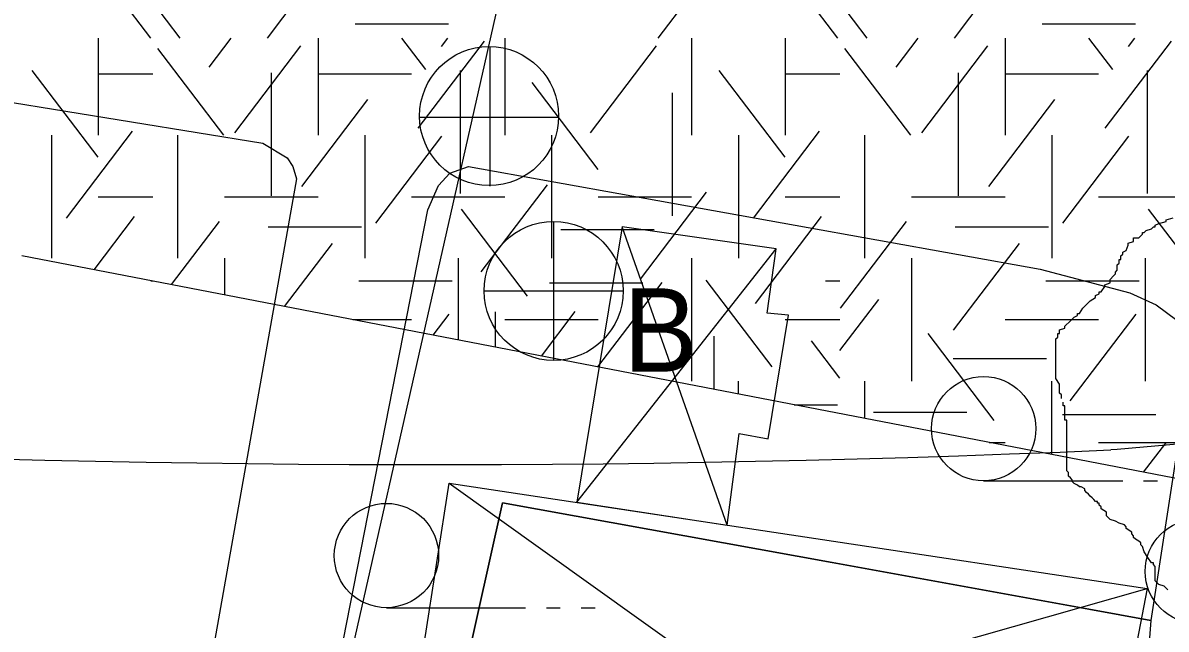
# Model space of a CAD drawing. Extents: x 419101 to 420177, y 4451541 to 4452254.
# Drawn here: x 419766.26 to 419782.7, y 4451874.81 to 4451883.53 of the extents above; entities that cross this region are included whole.
import ezdxf

# ---------------------------------------------------------------- set-up
doc = ezdxf.new("R2010")
doc.units = 0
for name, color, linetype in [('1_PLAN_ONAMA_SINIRI', 7, 'Continuous'), ('2_KADASTRO', 7, 'Continuous'), ('3_HALİHAZIR', 7, 'Continuous'), ('Level 10', 7, 'Continuous'), ('Level 3', 7, 'Continuous'), ('Level 41', 7, 'Continuous'), ('Level 62', 7, 'Continuous')]:
    doc.layers.add(name, color=color, linetype=linetype)

msp = doc.modelspace()

# ---------------------------------------------------------------- linework, layer by layer
at = {"layer": '1_PLAN_ONAMA_SINIRI'}
msp.add_line((419781.992, 4451877.39), (419781.902, 4451877.384), dxfattribs=at)
msp.add_lwpolyline([(419842.849, 4451882.779), (419781.992, 4451877.39)], dxfattribs=at)
msp.add_arc((419772.081, 4452104.769), 227.597, 260.70974, 272.47309, dxfattribs=at)
at = {"layer": '2_KADASTRO'}
for points in [[(419759.111, 4451874.282), (419762.553, 4451893.022), (419762.975, 4451895.317), (419776.403, 4451891.967), (419783.47, 4451890.204), (419784.306, 4451886.857), (419782.476, 4451874.932), (419781.586, 4451875.093), (419777.895, 4451875.763), (419773.151, 4451876.624), (419772.058, 4451871.72), (419771.471, 4451871.836), (419759.378, 4451874.229)], [(419772.058, 4451871.72), (419773.151, 4451876.624), (419777.895, 4451875.763), (419781.586, 4451875.093), (419782.476, 4451874.932), (419782.31, 4451872.739), (419781.942, 4451869.764), (419781.675, 4451869.818), (419781.384, 4451869.876), (419780.697, 4451870.01)]]:
    msp.add_lwpolyline(points, close=True, dxfattribs=at)
at = {"layer": '3_HALİHAZIR'}
for p, q in [((419772.975, 4451881.178), (419772.975, 4451883.178)), ((419771.955, 4451882.168), (419773.955, 4451882.168)), ((419773.888, 4451880.671), (419773.888, 4451878.671)), ((419776.382, 4451876.304), (419774.874, 4451880.593)), ((419774.221, 4451876.631), (419777.087, 4451880.275)), ((419772.888, 4451879.671), (419774.888, 4451879.671)), ((419772.387, 4451876.908), (419781.465, 4451870.409)), ((419780.071, 4451876.94), (419782.071, 4451876.94)), ((419782.371, 4451876.94), (419782.571, 4451876.94)), ((419771.676, 4451872.341), (419782.424, 4451875.392)), ((419771.484, 4451875.115), (419773.484, 4451875.115)), ((419773.784, 4451875.115), (419773.984, 4451875.115)), ((419774.284, 4451875.115), (419774.484, 4451875.115))]:
    msp.add_line(p, q, dxfattribs=at)
for points in [[(419759.591, 4451874.725), (419758.475, 4451874.972), (419759.632, 4451880.219), (419759.97, 4451880.958), (419761.907, 4451882.947), (419762.075, 4451883.015), (419762.146, 4451883.021), (419769.704, 4451881.794), (419770.058, 4451881.585), (419770.137, 4451881.459), (419770.191, 4451881.282), (419768.71, 4451872.926)], [(419770.457, 4451872.581), (419772.077, 4451880.838), (419772.233, 4451881.185), (419772.396, 4451881.366), (419772.664, 4451881.458), (419780.886, 4451879.982), (419782.172, 4451879.643), (419782.552, 4451879.47), (419782.85, 4451879.248)]]:
    msp.add_lwpolyline(points, dxfattribs=at)
for points in [[(419774.221, 4451876.631), (419776.382, 4451876.304), (419776.556, 4451877.621), (419776.975, 4451877.542), (419777.267, 4451879.323), (419776.958, 4451879.351), (419777.087, 4451880.275), (419774.874, 4451880.593)], [(419771.676, 4451872.341), (419772.387, 4451876.908), (419782.424, 4451875.392), (419781.465, 4451870.409)]]:
    msp.add_lwpolyline(points, close=True, dxfattribs=at)
for centre, radius in [((419772.96, 4451882.186), 1), ((419773.888, 4451879.671), 1), ((419780.071, 4451877.69), 0.75), ((419771.484, 4451875.865), 0.75), ((419783.143, 4451875.637), 0.75)]:
    msp.add_circle(centre, radius, dxfattribs=at)
at = {"layer": 'Level 10'}
msp.add_lwpolyline([(419822.258, 4451726.513), (419833.485, 4451749.755), (419825.109, 4451754.045), (419837.782, 4451781.64), (419829.05, 4451785.752), (419831.545, 4451792.367), (419821.03, 4451797.373), (419817.644, 4451790.221), (419809.089, 4451795.049), (419767.565, 4451777.886), (419755.344, 4451810.228), (419782.076, 4451819.704), (419780.107, 4451841.764), (419779.395, 4451861.43), (419768.523, 4451863.576), (419780.134, 4451914.941)], dxfattribs=at)
at = {"layer": 'Level 3'}
for points in [[(419781.189, 4451878.124), (419781.189, 4451878.15), (419781.189, 4451878.175), (419781.163, 4451878.201), (419781.163, 4451878.227), (419781.163, 4451878.253), (419781.163, 4451878.279), (419781.163, 4451878.305), (419781.163, 4451878.331), (419781.111, 4451878.409), (419781.111, 4451878.487), (419781.111, 4451878.513), (419781.111, 4451878.591), (419781.111, 4451878.669), (419781.111, 4451878.695), (419781.111, 4451878.721), (419781.111, 4451878.747), (419781.111, 4451878.773), (419781.111, 4451878.799), (419781.111, 4451878.825), (419781.111, 4451878.851), (419781.111, 4451878.877), (419781.111, 4451878.903), (419781.111, 4451878.981), (419781.137, 4451879.006), (419781.137, 4451879.032), (419781.137, 4451879.058), (419781.163, 4451879.058), (419781.163, 4451879.084), (419781.163, 4451879.11), (419781.241, 4451879.136), (419781.241, 4451879.162), (419781.319, 4451879.24), (419781.371, 4451879.292), (419781.422, 4451879.318), (419781.422, 4451879.344), (419781.448, 4451879.344), (419781.5, 4451879.422), (419781.552, 4451879.474), (419781.604, 4451879.526), (419781.682, 4451879.578), (419781.682, 4451879.604), (419781.734, 4451879.63), (419781.734, 4451879.656), (419781.76, 4451879.656), (419781.812, 4451879.734), (419781.812, 4451879.76), (419781.889, 4451879.786), (419781.889, 4451879.811), (419781.889, 4451879.837), (419781.941, 4451879.889), (419781.967, 4451879.915), (419781.967, 4451879.941), (419781.993, 4451879.967), (419781.993, 4451879.993), (419781.993, 4451880.019), (419781.993, 4451880.045), (419782.019, 4451880.071), (419782.019, 4451880.097), (419782.019, 4451880.123), (419782.045, 4451880.123), (419782.045, 4451880.149), (419782.045, 4451880.175), (419782.071, 4451880.201), (419782.071, 4451880.227), (419782.123, 4451880.253), (419782.149, 4451880.331), (419782.149, 4451880.357), (419782.227, 4451880.383), (419782.227, 4451880.409), (419782.227, 4451880.435), (419782.304, 4451880.435), (419782.356, 4451880.487), (419782.356, 4451880.513), (419782.382, 4451880.513), (419782.408, 4451880.539), (419782.486, 4451880.565), (419782.512, 4451880.591), (419782.538, 4451880.591), (419782.538, 4451880.617), (419782.59, 4451880.642), (419782.694, 4451880.668), (419782.694, 4451880.694), (419782.797, 4451880.72)], [(419782.72, 4451875.371), (419782.668, 4451875.423), (419782.59, 4451875.449), (419782.564, 4451875.475), (419782.538, 4451875.501), (419782.538, 4451875.527), (419782.538, 4451875.605), (419782.538, 4451875.683), (419782.538, 4451875.708), (419782.512, 4451875.734), (419782.512, 4451875.76), (419782.486, 4451875.76), (419782.434, 4451875.838), (419782.382, 4451875.916), (419782.356, 4451875.994), (419782.33, 4451876.02), (419782.33, 4451876.046), (419782.304, 4451876.072), (419782.253, 4451876.098), (419782.227, 4451876.124), (419782.227, 4451876.15), (419782.201, 4451876.176), (419782.201, 4451876.202), (419782.123, 4451876.254), (419782.123, 4451876.28), (419782.097, 4451876.306), (419782.019, 4451876.332), (419781.967, 4451876.358), (419781.889, 4451876.384), (419781.863, 4451876.41), (419781.838, 4451876.436), (419781.838, 4451876.462), (419781.838, 4451876.488), (419781.76, 4451876.539), (419781.76, 4451876.565), (419781.734, 4451876.591), (419781.734, 4451876.617), (419781.708, 4451876.617), (419781.708, 4451876.643), (419781.682, 4451876.643), (419781.656, 4451876.669), (419781.63, 4451876.695), (419781.604, 4451876.721), (419781.578, 4451876.747), (419781.552, 4451876.773), (419781.526, 4451876.799), (419781.526, 4451876.825), (419781.474, 4451876.851), (419781.448, 4451876.851), (419781.422, 4451876.877), (419781.371, 4451876.903), (419781.345, 4451876.929), (419781.345, 4451876.955), (419781.319, 4451876.981), (419781.293, 4451877.007), (419781.293, 4451877.033), (419781.293, 4451877.059), (419781.267, 4451877.085), (419781.267, 4451877.111), (419781.267, 4451877.137), (419781.267, 4451877.215), (419781.267, 4451877.267), (419781.267, 4451877.293), (419781.267, 4451877.319), (419781.267, 4451877.344), (419781.267, 4451877.37), (419781.267, 4451877.396), (419781.267, 4451877.422), (419781.267, 4451877.448), (419781.267, 4451877.474), (419781.267, 4451877.5), (419781.267, 4451877.526), (419781.267, 4451877.552), (419781.267, 4451877.578), (419781.267, 4451877.604), (419781.267, 4451877.63), (419781.267, 4451877.656), (419781.267, 4451877.682), (419781.267, 4451877.76), (419781.267, 4451877.786), (419781.267, 4451877.812), (419781.241, 4451877.812), (419781.241, 4451877.838), (419781.241, 4451877.864), (419781.241, 4451877.89), (419781.241, 4451877.916), (419781.241, 4451877.942), (419781.241, 4451877.968), (419781.241, 4451877.994), (419781.241, 4451878.02), (419781.215, 4451878.02), (419781.215, 4451878.046), (419781.215, 4451878.072)]]:
    msp.add_lwpolyline(points, dxfattribs=at)
at = {"layer": 'Level 41'}
for p, q in [((419768.095, 4451883.307), (419767.293, 4451884.363)), ((419769.771, 4451883.307), (419770.6, 4451884.398)), ((419777.974, 4451883.307), (419777.172, 4451884.363)), ((419779.65, 4451883.307), (419780.479, 4451884.398)), ((419775.391, 4451883.307), (419775.928, 4451884.013)), ((419768.518, 4451883.307), (419768.124, 4451883.825)), ((419778.397, 4451883.307), (419778.003, 4451883.825)), ((419771.033, 4451883.513), (419772.376, 4451883.513)), ((419780.912, 4451883.513), (419782.255, 4451883.513)), ((419767.336, 4451883.307), (419767.336, 4451881.909)), ((419767.336, 4451883.307), (419767.336, 4451881.909)), ((419768.934, 4451882.89), (419769.251, 4451883.307)), ((419770.5, 4451883.307), (419770.5, 4451881.909)), ((419772.049, 4451882.855), (419771.705, 4451883.307)), ((419772.275, 4451883.187), (419772.366, 4451883.307)), ((419773.186, 4451883.307), (419773.186, 4451881.909)), ((419775.872, 4451883.307), (419775.872, 4451881.909)), ((419777.215, 4451883.307), (419777.215, 4451881.909)), ((419777.215, 4451883.307), (419777.215, 4451881.909)), ((419778.813, 4451882.89), (419779.13, 4451883.307)), ((419780.379, 4451883.307), (419780.379, 4451881.909)), ((419781.928, 4451882.855), (419781.584, 4451883.307)), ((419782.154, 4451883.187), (419782.245, 4451883.307)), ((419769.145, 4451881.909), (419768.196, 4451883.159)), ((419769.305, 4451881.944), (419770.254, 4451883.194)), ((419771.942, 4451882.013), (419772.892, 4451883.263)), ((419774.419, 4451881.944), (419775.368, 4451883.194)), ((419779.024, 4451881.909), (419778.075, 4451883.159)), ((419779.184, 4451881.944), (419780.133, 4451883.194)), ((419781.821, 4451882.013), (419782.771, 4451883.263)), ((419767.337, 4451881.593), (419766.388, 4451882.842)), ((419767.336, 4451882.793), (419768.124, 4451882.793)), ((419769.825, 4451882.805), (419769.825, 4451881.038)), ((419770.5, 4451882.793), (419771.843, 4451882.793)), ((419772.542, 4451882.84), (419772.542, 4451881.073)), ((419777.216, 4451881.593), (419776.267, 4451882.842)), ((419777.215, 4451882.793), (419778.003, 4451882.793)), ((419779.704, 4451882.805), (419779.704, 4451881.038)), ((419780.379, 4451882.793), (419781.722, 4451882.793)), ((419782.421, 4451882.84), (419782.421, 4451881.073)), ((419774.526, 4451881.418), (419773.577, 4451882.667)), ((419775.59, 4451882.519), (419775.59, 4451880.752)), ((419770.265, 4451881.172), (419771.214, 4451882.422)), ((419780.144, 4451881.172), (419781.093, 4451882.422)), ((419766.885, 4451880.716), (419767.834, 4451881.966)), ((419776.764, 4451880.716), (419777.713, 4451881.966)), ((419766.665, 4451881.909), (419766.665, 4451880.142)), ((419766.665, 4451881.909), (419766.665, 4451880.142)), ((419768.486, 4451880.142), (419768.486, 4451881.909)), ((419771.172, 4451881.909), (419771.172, 4451880.142)), ((419771.331, 4451880.647), (419772.28, 4451881.897)), ((419773.858, 4451881.909), (419773.858, 4451880.142)), ((419776.544, 4451881.909), (419776.544, 4451880.142)), ((419776.544, 4451881.909), (419776.544, 4451880.142)), ((419778.365, 4451880.142), (419778.365, 4451881.909)), ((419781.051, 4451881.909), (419781.051, 4451880.142)), ((419781.21, 4451880.647), (419782.159, 4451881.897)), ((419772.848, 4451879.946), (419773.799, 4451881.195)), ((419767.336, 4451881.025), (419768.124, 4451881.025)), ((419769.157, 4451881.025), (419770.5, 4451881.025)), ((419771.843, 4451881.025), (419773.186, 4451881.025)), ((419774.529, 4451881.025), (419775.872, 4451881.025)), ((419775.139, 4451879.841), (419776.088, 4451881.091)), ((419777.215, 4451881.025), (419778.003, 4451881.025)), ((419779.036, 4451881.025), (419780.379, 4451881.025)), ((419781.722, 4451881.025), (419783.065, 4451881.025)), ((419773.514, 4451879.596), (419772.564, 4451880.845)), ((419783.393, 4451879.596), (419782.443, 4451880.845)), ((419767.28, 4451879.976), (419767.861, 4451880.739)), ((419768.392, 4451879.761), (419769.083, 4451880.67)), ((419776.79, 4451879.49), (419777.74, 4451880.739)), ((419778.013, 4451879.421), (419778.962, 4451880.67)), ((419769.781, 4451880.591), (419771.124, 4451880.591)), ((419773.989, 4451880.555), (419775.332, 4451880.555)), ((419779.66, 4451880.591), (419781.003, 4451880.591)), ((419770.019, 4451879.447), (419770.708, 4451880.354)), ((419779.638, 4451879.104), (419780.587, 4451880.354)), ((419769.157, 4451880.142), (419769.157, 4451879.613)), ((419772.515, 4451880.142), (419772.515, 4451878.965)), ((419775.872, 4451880.142), (419775.872, 4451878.375)), ((419779.036, 4451880.142), (419779.036, 4451878.375)), ((419782.394, 4451880.142), (419782.394, 4451878.375)), ((419768.097, 4451879.818), (419768.124, 4451879.818)), ((419771.087, 4451879.818), (419772.43, 4451879.818)), ((419773.829, 4451879.785), (419775.172, 4451879.785)), ((419774.524, 4451878.577), (419775.449, 4451879.794)), ((419777.029, 4451878.578), (419776.08, 4451879.827)), ((419777.799, 4451879.818), (419778.003, 4451879.818)), ((419780.966, 4451879.818), (419782.309, 4451879.818)), ((419778.003, 4451878.812), (419778.562, 4451879.548)), ((419772.155, 4451879.035), (419772.386, 4451879.338)), ((419773.047, 4451879.37), (419773.047, 4451878.862)), ((419773.711, 4451878.734), (419774.196, 4451879.373)), ((419781.315, 4451878.088), (419782.265, 4451879.338)), ((419770.998, 4451879.258), (419771.843, 4451879.258)), ((419773.186, 4451879.258), (419774.529, 4451879.258)), ((419777.215, 4451879.258), (419778.003, 4451879.258)), ((419780.379, 4451879.258), (419781.722, 4451879.258)), ((419776.19, 4451879.02), (419776.19, 4451878.256)), ((419780.223, 4451877.807), (419779.274, 4451879.057)), ((419778.003, 4451878.418), (419777.597, 4451878.952)), ((419779.633, 4451878.698), (419780.976, 4451878.698)), ((419776.544, 4451878.187), (419776.544, 4451878.375)), ((419778.365, 4451877.836), (419778.365, 4451878.375)), ((419781.051, 4451877.317), (419781.051, 4451878.375)), ((419777.349, 4451878.032), (419777.969, 4451878.032)), ((419778.488, 4451877.926), (419779.831, 4451877.926)), ((419781.205, 4451877.892), (419782.548, 4451877.892)), ((419780.151, 4451877.491), (419780.379, 4451877.491)), ((419781.722, 4451877.491), (419783.065, 4451877.491)), ((419782.372, 4451877.062), (419782.69, 4451877.48))]:
    msp.add_line(p, q, dxfattribs=at)
at = {"layer": 'Level 62'}
msp.add_line((419809.184, 4451871.886), (419766.243, 4451880.176), dxfattribs=at)

# ---------------------------------------------------------------- texts
at = {"layer": '3_HALİHAZIR'}
msp.add_text('B', height=1.2, dxfattribs=at).set_placement((419774.888, 4451878.509))

doc.saveas('drawing.dxf')
